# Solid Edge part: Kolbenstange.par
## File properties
Username: bmolnar
Dokumentum tartalom típus: 0
Author: bmolnar
Last saved by: bmolnar
Revision: 86
Sűrűség: 0,000 kg/m^3
Pontosság: 0,990
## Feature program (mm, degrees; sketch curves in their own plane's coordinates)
base feature "unnamed BaseFeature 1"
sketch for "unnamed Protrusion 1" plane through (0, 0, -17.4) normal (0, 0, -1) x-axis (0, -1, 0)
  circle centre (0, 0) radius 20
extrude "unnamed Protrusion 1" add finite 6.45 along +normal
sketch for "Furat_1" plane through (0, 0, 64.9) normal (0, 0, 1) x-axis (0, 1, 0)
  hole centre (0, 0) bore radius 2.4585
hole "Furat_1" nominal diameter 6 finite  VBottomAngle = 118 deg; ThreadDepth = 12.5 mm
chamfer "Letörés_1" setback 0.5  SetBackValue2 = 45 deg
sketch for "Kihúzás_2" #1 plane through (0, 0, -17.4) normal (0, 0, -1) x-axis (0, -1, 0)
  circle centre (0, 0) radius 6
sketch for "Kihúzás_2" #2 plane through (0, 0, -17.4) normal (0, 0, -1) x-axis (0, -1, 0)
  circle centre (0, 0) radius 20
extrude "Kihúzás_2" add finite 33.55 along -normal
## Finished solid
Body 1: solid body, 17 faces, 23 edges, 8 vertices.
  Faces by surface: plane 7, cylinder 5, cone 3, torus 2
  Edges by curve: circle 13, line 6, curve on surface 2, ellipse 2
Bounding box of the edges (mm; curved faces can reach further): 40.000 x 40.000 x 91.250, from (-20, -20, -23.85) to (20, 20, 67.4).
Cylindrical faces by radius (mm): R2.4585 x2, R3.125 x1, R6 x1, R20 x1
Conical faces (half-angle, radius in mm at the cone's reference point): 45 deg R2.9585 x1, 45 deg R3.225 x1, 59 deg R2.4585 x1
Toroidal faces (ring radius, tube radius in mm): R2.925 r0.2 x1, R4.7 r1.3 x1
Planar faces by outward normal: +x 1, +z 2, -x 1, -z 1, oblique 2
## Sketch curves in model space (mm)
circle centre (0, 0, -17.4) radius 6
circle centre (0, 0, -17.4) radius 20
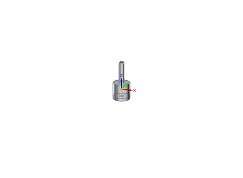
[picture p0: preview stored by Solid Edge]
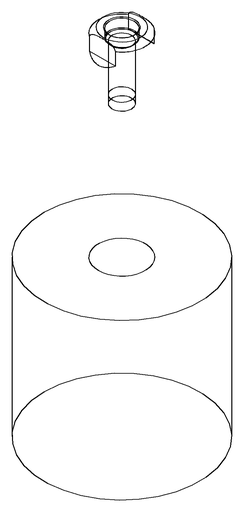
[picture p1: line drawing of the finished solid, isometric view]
